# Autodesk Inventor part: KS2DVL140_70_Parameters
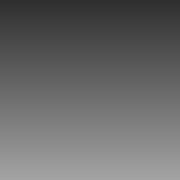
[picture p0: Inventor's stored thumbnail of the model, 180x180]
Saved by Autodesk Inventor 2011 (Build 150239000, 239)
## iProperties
Created: 2010-11
Document SubType Name: Modeling
Designer: TB
Density: 1 g/cm^3
Slaglengde: 100,000 mm
Vinkel_Minusport: 0.00 deg
Forlengelse_rør: 0.000 mm
Minusport2: 180.00 deg
Author: TB
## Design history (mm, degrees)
other parameters: "Slaglengde" = 100 [user parameter], "Forlengelse_rør" = 0 [user parameter], "Vinkel_Minusport" = 0 deg [user parameter], "Minusport2" = 180 deg [user parameter]
